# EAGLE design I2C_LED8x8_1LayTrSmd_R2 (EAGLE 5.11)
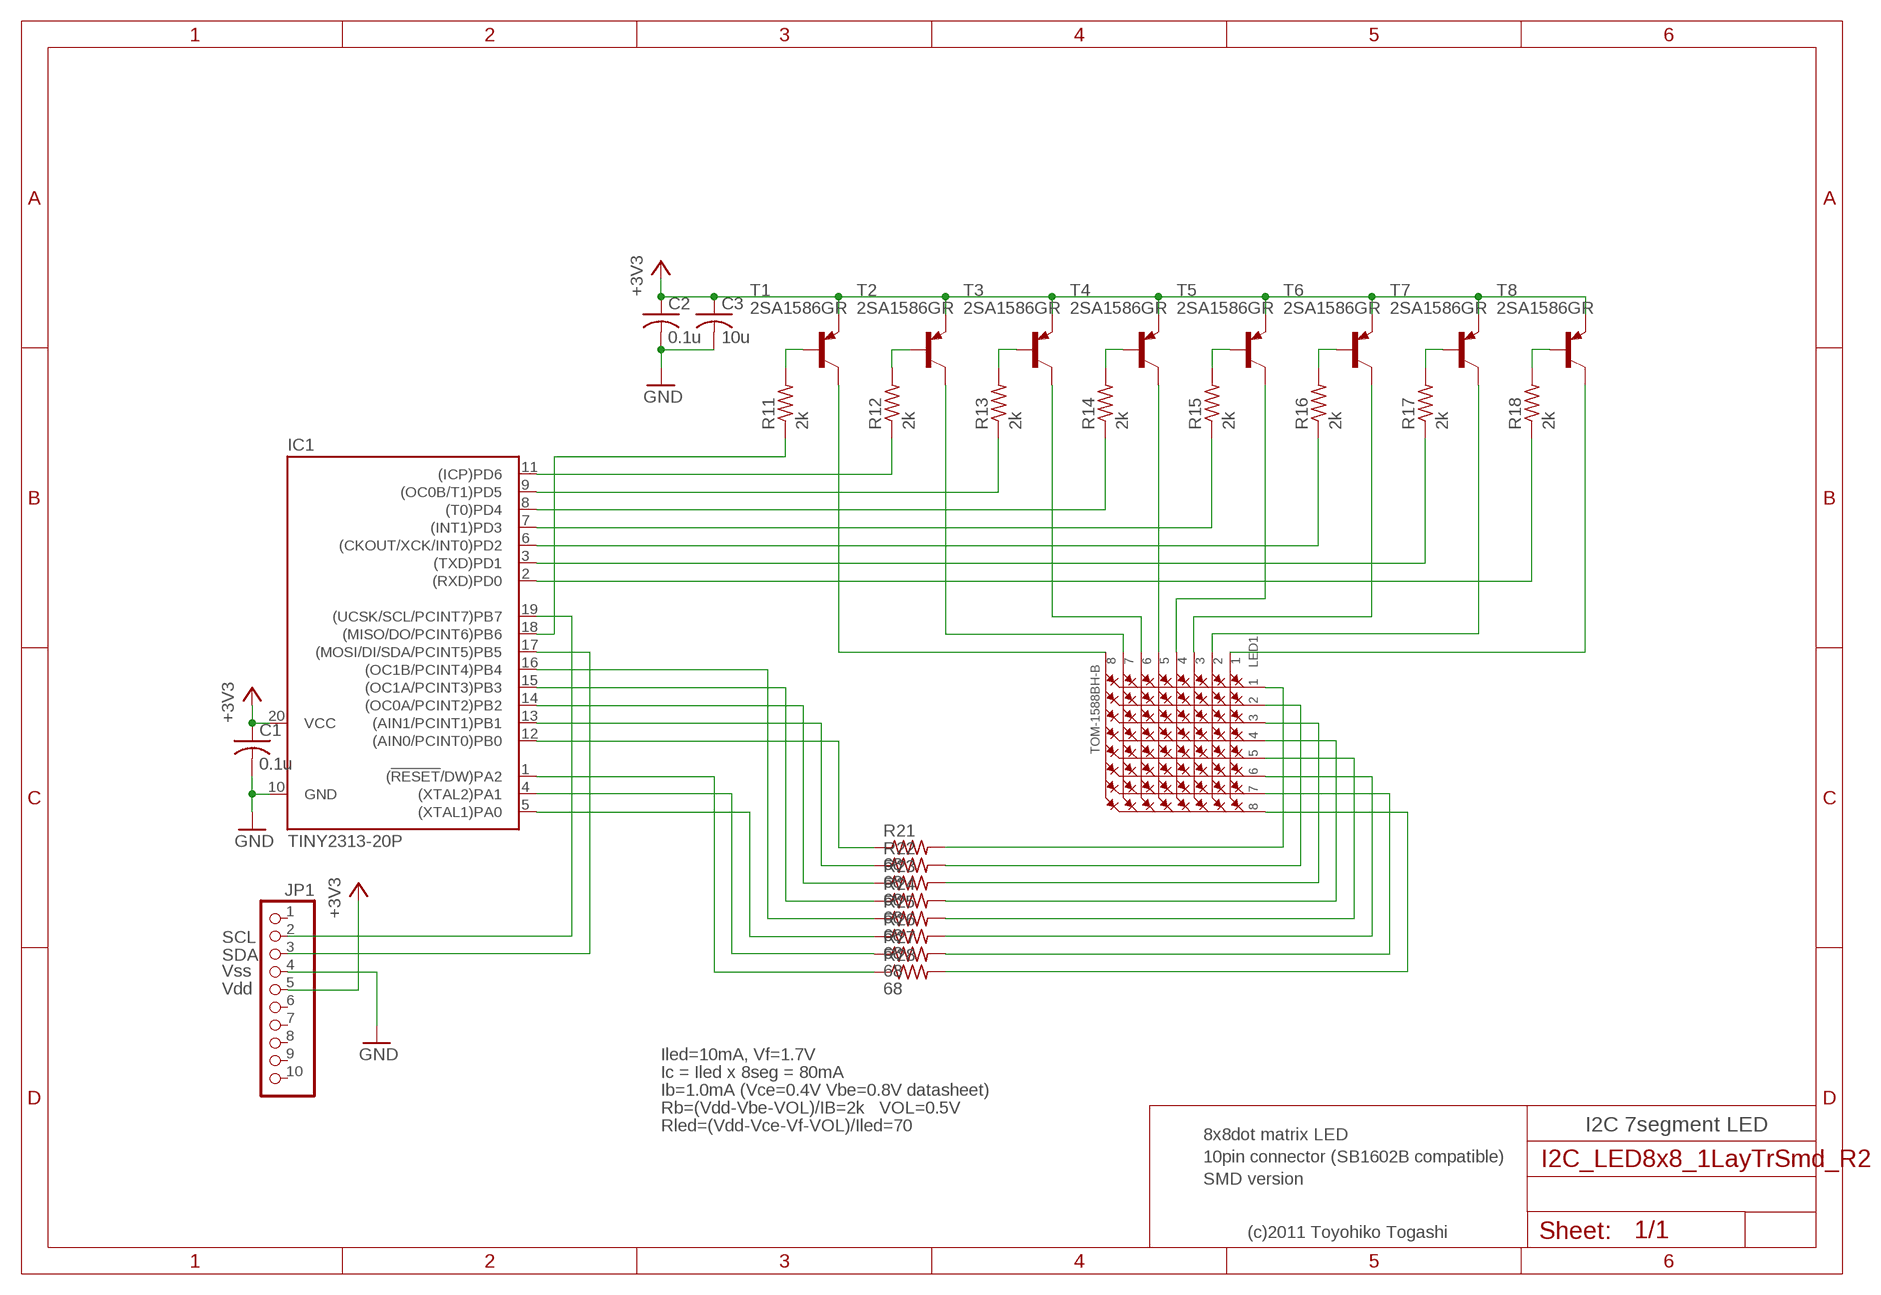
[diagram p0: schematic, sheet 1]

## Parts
C1  0.1u  C-USC0805  [C0805]
C2  0.1u  C-USC0805  [C0805]
C3  10u  C-USC1206  [C1206]
IC1  TINY2313-20P  [DIL20]
JP1  PINHD-1X10  [1X10]
LED1  TOM-1588BH-B  [C-4880X]
R11  2k  R-US_R0603  [R0603]
R12  2k  R-US_R0603  [R0603]
R13  2k  R-US_R0603  [R0603]
R14  2k  R-US_R0603  [R0603]
R15  2k  R-US_R0603  [R0603]
R16  2k  R-US_R0603  [R0603]
R17  2k  R-US_R0603  [R0603]
R18  2k  R-US_R0603  [R0603]
R21  68  R-US_R0603  [R0603]
R22  68  R-US_R0603  [R0603]
R23  68  R-US_R0603  [R0603]
R24  68  R-US_R0603  [R0603]
R25  68  R-US_R0603  [R0603]
R26  68  R-US_R0603  [R0603]
R27  68  R-US_R0603  [R0603]
R28  68  R-US_R0603  [R0603]
T1  2SA1586GR  -PNP-SOT23-BCE  [SOT23-BCE]
T2  2SA1586GR  -PNP-SOT23-BCE  [SOT23-BCE]
T3  2SA1586GR  -PNP-SOT23-BCE  [SOT23-BCE]
T4  2SA1586GR  -PNP-SOT23-BCE  [SOT23-BCE]
T5  2SA1586GR  -PNP-SOT23-BCE  [SOT23-BCE]
T6  2SA1586GR  -PNP-SOT23-BCE  [SOT23-BCE]
T7  2SA1586GR  -PNP-SOT23-BCE  [SOT23-BCE]
T8  2SA1586GR  -PNP-SOT23-BCE  [SOT23-BCE]

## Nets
+3V3: C1.1 C2.1 C3.1 IC1.20(VCC) JP1.5 T1.E T2.E T3.E T4.E T5.E T6.E T7.E T8.E
GND: C1.2 C2.2 C3.2 IC1.10(GND) JP1.4
N$1: LED1.P$13(COL1) R21.2
N$2: LED1.P$3(COL2) R22.2
N$3: IC1.19((UCSK/SCL/PCINT7)PB7) JP1.2
N$4: IC1.17((MOSI/DI/SDA/PCINT5)PB5) JP1.3
N$5: LED1.P$4(COL3) R23.2
N$6: LED1.P$10(COL4) R24.2
N$7: LED1.P$6(COL5) R25.2
N$8: LED1.P$11(COL6) R26.2
N$9: LED1.P$15(COL7) R27.2
N$10: LED1.P$16(COL8) R28.2
N$11: LED1.P$5(ROW8) T1.C
N$12: LED1.P$2(ROW7) T2.C
N$13: R11.2 T1.B
N$14: IC1.5((XTAL1)PA0) R26.1
N$15: IC1.4((XTAL2)PA1) R27.1
N$16: IC1.1((!RESET!/DW)PA2) R28.1
N$17: IC1.12((AIN0/PCINT0)PB0) R21.1
N$18: LED1.P$7(ROW6) T3.C
N$19: IC1.13((AIN1/PCINT1)PB1) R22.1
N$20: IC1.14((OC0A/PCINT2)PB2) R23.1
N$21: IC1.15((OC1A/PCINT3)PB3) R24.1
N$22: IC1.16((OC1B/PCINT4)PB4) R25.1
N$23: LED1.P$1(ROW5) T4.C
N$24: LED1.P$12(ROW4) T5.C
N$25: IC1.18((MISO/DO/PCINT6)PB6) R11.1
N$26: R18.2 T8.B
N$27: LED1.P$8(ROW3) T6.C
N$28: IC1.2((RXD)PD0) R18.1
N$29: LED1.P$14(ROW2) T7.C
N$30: LED1.P$9(ROW1) T8.C
N$35: R12.2 T2.B
N$48: R13.2 T3.B
N$50: IC1.3((TXD)PD1) R17.1
N$53: IC1.7((INT1)PD3) R15.1
N$54: IC1.9((OC0B/T1)PD5) R13.1
N$60: R14.2 T4.B
N$72: R15.2 T5.B
N$84: R16.2 T6.B
N$96: R17.2 T7.B
N$98: IC1.11((ICP)PD6) R12.1
N$100: IC1.8((T0)PD4) R14.1
N$102: IC1.6((CKOUT/XCK/INT0)PD2) R16.1
Unconnected: JP1.1 JP1.6 JP1.7 JP1.8 JP1.9 JP1.10

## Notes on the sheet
- SCL
- SDA
- Vss
- Vdd
- Iled=10mA, Vf=1.7V
- Ic = Iled x 8seg = 80mA
- Ib=1.0mA (Vce=0.4V Vbe=0.8V datasheet)
- Rb=(Vdd-Vbe-VOL)/IB=2k   VOL=0.5V
- Rled=(Vdd-Vce-Vf-VOL)/Iled=70 | I2C 7segment LED
- 8x8dot matrix LED
- 10pin connector (SB1602B compatible)
- SMD version
- (c)2011 Toyohiko Togashi

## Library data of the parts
C1-C3 = rcl:C-US: CAPACITOR, American symbol
IC1 = TOG:TINY2313: 8-bit AVR Microcontroller with 2K Bytes Flash Source: http://www.atmel.com .. doc2543.pdf
JP1 = pinhead:PINHD-1X10: PIN HEADER
LED1 = TOG:TOM-1588BH-B: PARALIGHT C-4880X 1.5x1.5inch 8x8dot matrix
R11-R18 R21-R28 = rcl:R-US_: RESISTOR, American symbol
T1-T8 = transistor:*-PNP-: PNP Transistror

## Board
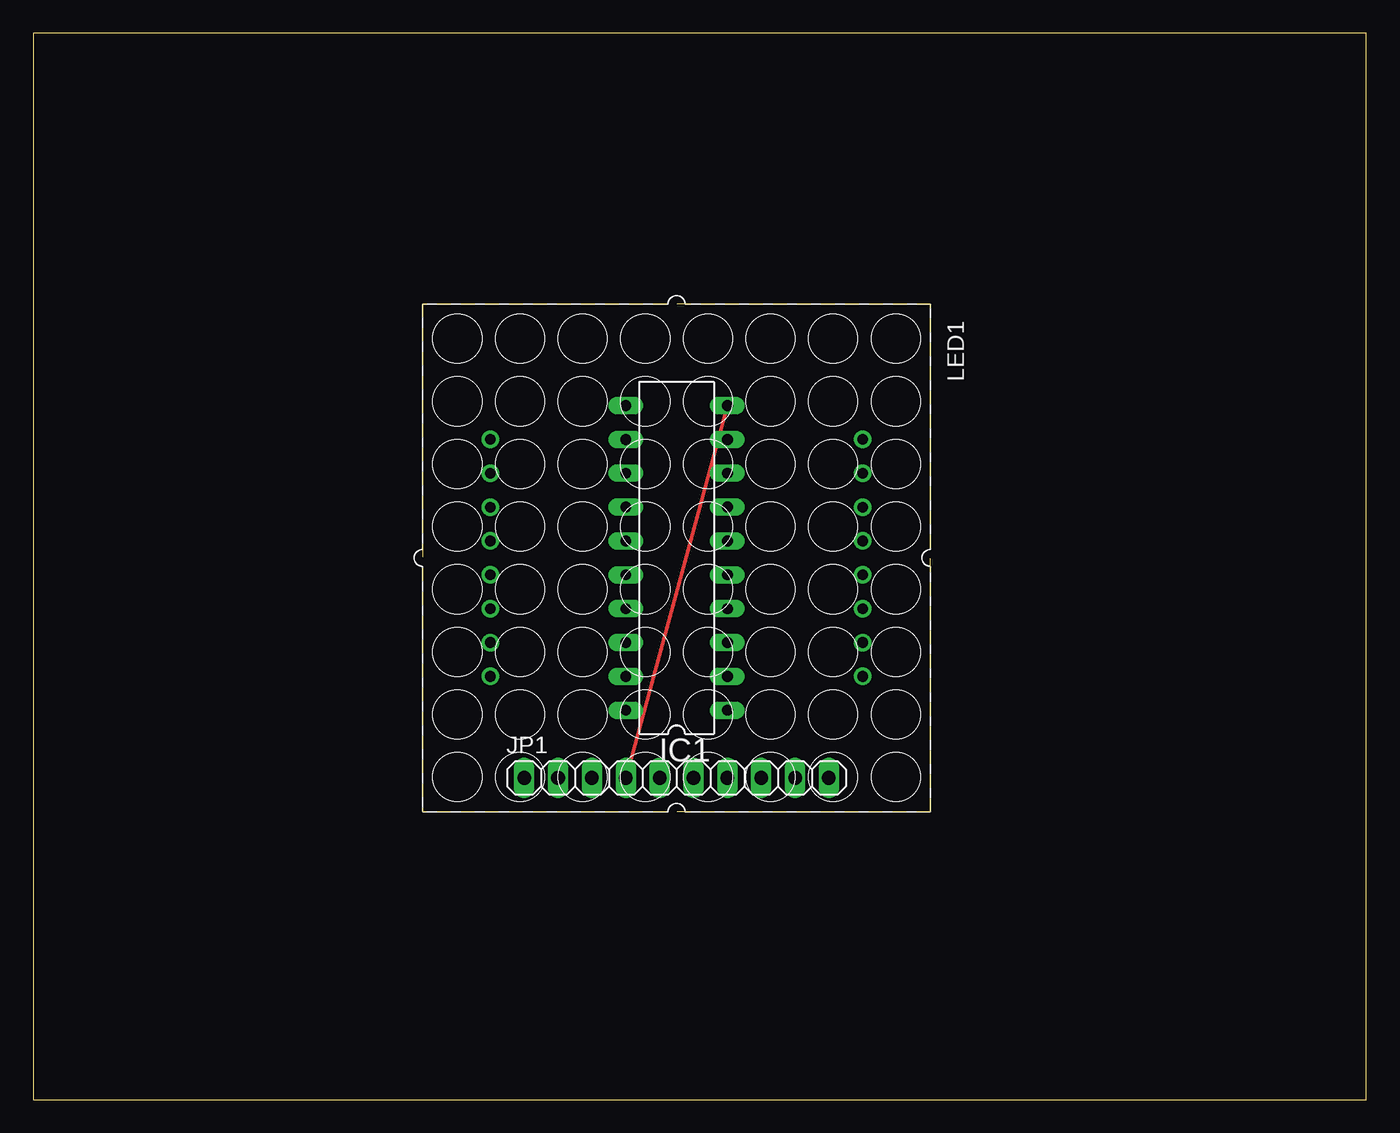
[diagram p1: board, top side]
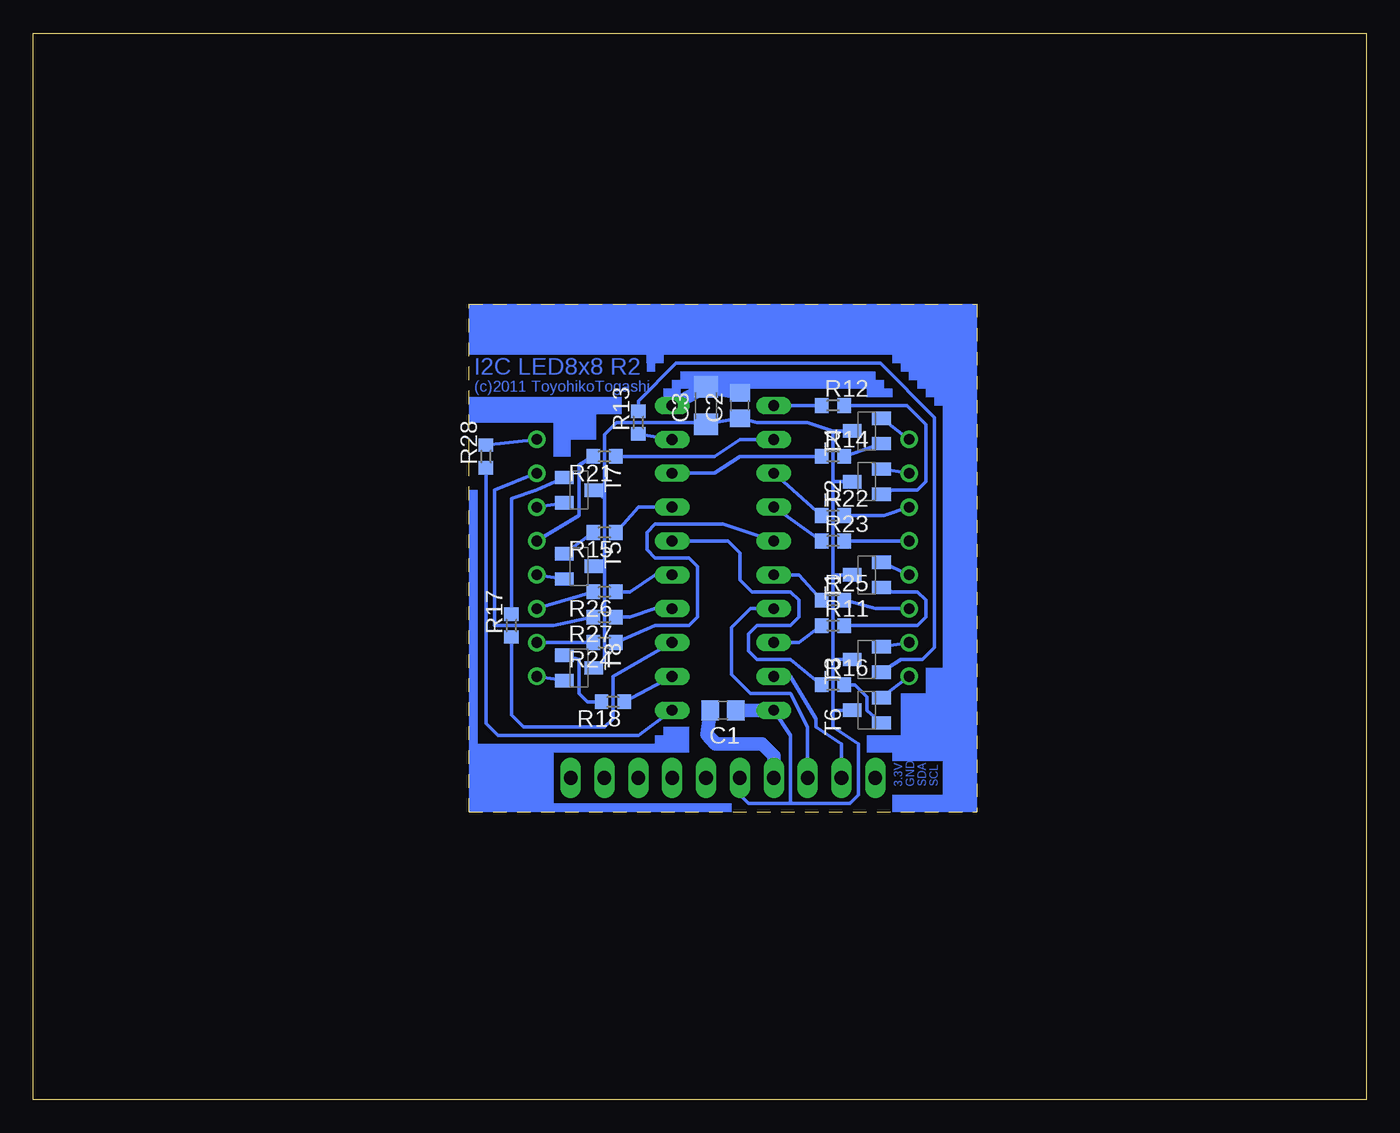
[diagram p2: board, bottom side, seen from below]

Size 100 x 80 mm. Coordinates in mm from the lower left corner, seen from the top.
Outline: 0,0 100,0 100,80 0,80 0,0
Outline: 29.21,59.69 29.21,21.59 67.31,21.59 67.31,59.69 29.21,59.69
Copper layers (1*16): Top 0.035mm / dielectric 1.5mm / Bottom 0.035mm
Design rules "default": minimum track width 10mil, minimum drill 24mil, track to track 8mil, track to pad 8mil, pad to pad 8mil, via to via 8mil, smd to smd 8mil, copper to edge 40mil, drill to drill 8mil, minimum pad ring 10mil, minimum via ring 8mil, stop-mask expansion 4mil, vias tented up to drill 0mil, thermal gap 10mil

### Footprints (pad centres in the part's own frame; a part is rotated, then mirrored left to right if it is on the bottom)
C0805 = smd 1.3 x 1.5: 1 -0.95,0; 2 0.95,0
C1206 = smd 1.6 x 1.8: 1 -1.4,0; 2 1.4,0
DIL20@1 = drill 0.813 long: 1 -11.43,-3.81; 2 -8.89,-3.81; 3 -6.35,-3.81; 4 -3.81,-3.81; 5 -1.27,-3.81; 6 1.27,-3.81; 7 3.81,-3.81; 8 6.35,-3.81; 9 8.89,-3.81; 10 11.43,-3.81; 11 11.43,3.81; 12 8.89,3.81; 13 6.35,3.81; 14 3.81,3.81; 15 1.27,3.81; 16 -1.27,3.81; 17 -3.81,3.81; 18 -6.35,3.81; 19 -8.89,3.81; 20 -11.43,3.81
1X10 = drill 1.016 long: 1 -11.43,0; 2 -8.89,0; 3 -6.35,0; 4 -3.81,0; 5 -1.27,0; 6 1.27,0; 7 3.81,0; 8 6.35,0; 9 8.89,0; 10 11.43,0
C-4880X = drill 0.8 round: P$1 -8.89,-13.97; P$2 -6.35,-13.97; P$3 -3.81,-13.97; P$4 -1.27,-13.97; P$5 1.27,-13.97; P$6 3.81,-13.97; P$7 6.35,-13.97; P$8 8.89,-13.97; P$9 8.89,13.97; P$10 6.35,13.97; P$11 3.81,13.97; P$12 1.27,13.97; P$13 -1.27,13.97; P$14 -3.81,13.97; P$15 -6.35,13.97; P$16 -8.89,13.97
R0603 = smd 1 x 1.1: 1 -0.85,0; 2 0.85,0
SOT23-BCE = smd 1 x 1.4: B -0.95,-1.1; C 0.95,-1.1; E 0,1.1

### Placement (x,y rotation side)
C1  48.26,29.21 180 bottom
C2  46.99,52.07 90 bottom
C3  49.53,52.07 90 bottom
IC1  TINY2313-20P  [DIL20@1]  48.26,40.64 90 top
JP1  48.26,24.13 0 top
LED1  48.26,40.64 270 top
R11  40.01,35.56 0 bottom
R12  40.01,52.07 0 bottom
R13  54.61,50.8 90 bottom
R14  40.01,48.26 0 bottom
R15  57.15,42.55 180 bottom
R16  40.01,31.11 0 bottom
R17  64.14,35.56 90 bottom
R18  56.52,29.84 180 bottom
R21  57.15,48.26 180 bottom
R22  40.01,43.81 0 bottom
R23  40.01,41.91 0 bottom
R24  57.15,34.29 180 bottom
R25  40.01,37.47 0 bottom
R26  57.15,38.1 180 bottom
R27  57.15,36.2 180 bottom
R28  66.04,48.26 90 bottom
T1  37.47,39.37 90 bottom
T2  37.47,46.35 90 bottom
T3  37.47,33.02 90 bottom
T4  37.47,50.16 90 bottom
T5  59.05,40.01 270 bottom
T6  37.47,29.21 90 bottom
T7  59.05,45.72 270 bottom
T8  59.05,32.38 270 bottom

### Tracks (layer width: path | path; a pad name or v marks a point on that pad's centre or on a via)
+3V3
  Bottom 0.254: T8.E 57.15,33.02 57.15,40.01 | 57.15,45.09 57.15,40.01 | 57.15,45.09 T7.E | 57.15,40.01 T5.E | IC1.20 43.18,27.3 43.18,22.23 | 43.18,22.23 38.73,22.23 38.1,22.86 38.1,26.67 40.01,27.94 40.01,29.21 | 40.01,29.21 40.01,33.02 | 40.01,33.02 40.01,39.37 | 40.01,39.37 40.01,46.35 | 40.01,46.35 40.01,50.16 | 40.01,50.16 T4.E | 40.01,46.35 T2.E | 40.01,39.37 T1.E | 40.01,33.02 T3.E | 40.01,29.21 T6.E | 57.15,45.09 57.15,49.9 56.25,50.8 50.16,50.8 C3.1 C2.1 45.72,50.8 41.91,50.8 40.01,50.16 | 43.18,22.23 46.35,22.23 46.99,22.86 JP1.5
  Bottom 1.016: IC1.20 C1.1
GND
  Top 0.254: JP1.4 IC1.10
  Bottom 1.016: IC1.10 C3.2 C2.2 | JP1.4 44.45,25.77 45.35,26.67 48.81,26.67 49.44,27.38 C1.2
N$1
  Bottom 0.254: LED1.P$13 59.05,43.81 59.05,47.62 R21.2
N$2
  Bottom 0.254: R22.2 36.2,43.81 LED1.P$3
N$3
  Bottom 0.254: JP1.2 39.37,26.67 41.27,27.94 41.27,28.57 43.18,31.75 IC1.19
N$4
  Bottom 0.254: JP1.3 41.91,27.94 43.18,30.48 46.2,30.48 47.62,31.9 47.62,35.41 46.2,36.83 IC1.17
N$5
  Bottom 0.254: LED1.P$4 R23.2
N$6
  Bottom 0.254: LED1.P$10 R24.2
N$7
  Bottom 0.254: LED1.P$6 36.83,36.83 R25.2
N$8
  Bottom 0.254: LED1.P$11 R26.2
N$9
  Bottom 0.254: R27.2 60.96,35.56 65.41,35.56 65.41,45.72 LED1.P$15
N$10
  Bottom 0.254: R28.2 LED1.P$16
N$11
  Bottom 0.254: LED1.P$5 T1.C
N$12
  Bottom 0.254: LED1.P$2 T2.C
N$13
  Bottom 0.254: R11.2 33.66,35.56 33.02,36.2 33.02,37.47 33.66,38.1 35.56,38.1 T1.B
N$14
  Bottom 0.254: R26.1 55.24,38.1 53.34,39.37 IC1.5
N$15
  Bottom 0.254: R27.1 55.24,36.2 53.34,36.83 IC1.4
N$16
  Bottom 0.254: IC1.1 54.61,27.3 65.14,27.3 66.04,28.2 R28.1
N$17
  Bottom 0.254: R21.1 48.9,48.26 46.99,49.53 IC1.12
N$18
  Bottom 0.254: LED1.P$7 T3.C
N$19
  Bottom 0.254: R22.1 IC1.13
N$20
  Bottom 0.254: R23.1 IC1.14
N$21
  Bottom 0.254: R24.1 53.34,35.56 50.8,35.56 50.16,36.2 50.16,40.01 50.8,40.64 53.34,40.64 53.98,41.27 53.98,42.55 53.34,43.18 48.26,43.18 IC1.15
N$22
  Bottom 0.254: IC1.16 42.55,39.37 R25.1
N$23
  Bottom 0.254: LED1.P$1 T4.C
N$24
  Bottom 0.254: LED1.P$12 T5.C
N$25
  Bottom 0.254: IC1.18 42.55,34.29 R11.1
N$26
  Bottom 0.254: R18.2 58.42,29.84 59.05,30.48 59.05,33.02 T8.B
N$27
  Bottom 0.254: LED1.P$8 T6.C
N$28
  Bottom 0.254: IC1.2 R18.1
N$29
  Bottom 0.254: T7.C LED1.P$14
N$30
  Bottom 0.254: LED1.P$9 T8.C
N$35
  Bottom 0.254: R12.2 34.44,52.07 33.02,50.65 33.02,46.35 33.66,45.72 35.56,45.72 T2.B
N$48
  Bottom 0.254: T3.B 34.92,33.02 33.28,33.02 32.38,33.92 32.38,51.18 36.45,55.24 51.77,55.24 54.61,52.41 R13.2
N$50
  Bottom 0.254: IC1.3 56.52,31.75 56.52,28.57 57.15,27.94 63.24,27.94 64.14,28.84 R17.1
N$53
  Bottom 0.254: R15.1 54.61,44.45 IC1.7
N$54
  Bottom 0.254: IC1.9 R13.1
N$60
  Bottom 0.254: T4.B R14.2
N$72
  Bottom 0.254: T5.B R15.2
N$84
  Bottom 0.254: T6.B 37.47,29.21 37.47,30.22 38.36,31.11 R16.2
N$96
  Bottom 0.254: T7.B 62.23,45.72 64.14,45.09 R17.2
N$98
  Bottom 0.254: R12.1 IC1.11
N$100
  Bottom 0.254: R14.1 46.99,48.26 48.9,46.99 IC1.8
N$102
  Bottom 0.254: R16.1 43.18,33.02 45.72,33.02 46.35,33.66 46.35,34.92 45.72,35.56 43.18,35.56 42.55,36.2 42.55,37.47 43.18,38.1 46.09,38.1 46.99,39 46.99,41.01 47.89,41.91 IC1.6
(copper drawn outside any net)
  shapes: Bottom area x30

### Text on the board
Bottom: I2C LED8x8 R2 | (c)2011 ToyohikoTogashi | SCL | SDA | GND | 3.3V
